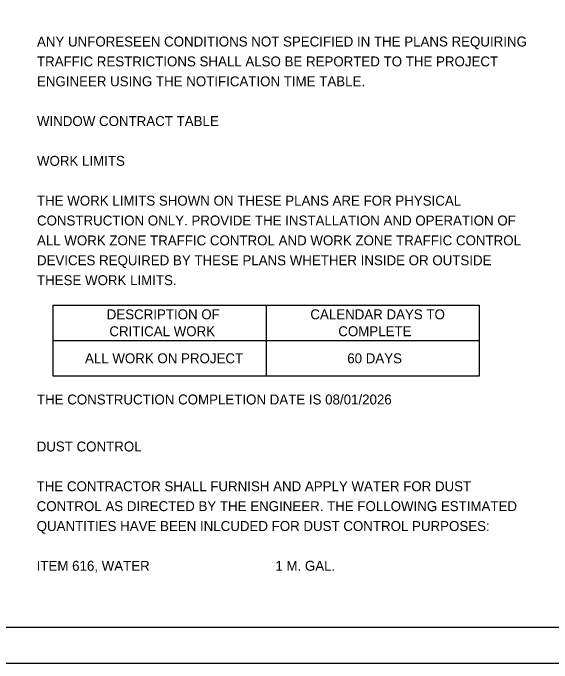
# Model space of a CAD drawing. Extents: x 0 to 34, y 0 to 22.
# Drawn here: x 16.9 to 24.49, y 0 to 9.15 of the extents above; entities that cross this region are included whole.
import ezdxf

# ---------------------------------------------------------------- set-up
doc = ezdxf.new("R2010")
doc.units = 0
for name, color, linetype in [('SH_Border', 7, 'Continuous'), ('SH_Cut_Line', 7, 'Continuous'), ('SH_Text', 7, 'Continuous')]:
    doc.layers.add(name, color=color, linetype=linetype)

msp = doc.modelspace()

# ---------------------------------------------------------------- linework, layer by layer
at = {"layer": 'SH_Border'}
msp.add_lwpolyline([(1.5, 21.5), (33.5, 21.5), (33.5, 0.5), (1.5, 0.5)], close=True, dxfattribs=at)
at = {"layer": 'SH_Cut_Line'}
msp.add_lwpolyline([(0, 0), (34, 0), (34, 22), (0, 22)], close=True, dxfattribs=at)
at = {"layer": 'SH_Text'}
for p, q in [((17.4658, 5.04), (23.4658, 5.04)), ((17.4658, 4.04), (17.4658, 5.04)), ((20.4658, 5.04), (20.4658, 4.04)), ((23.4658, 5.04), (23.4658, 4.04)), ((17.4658, 4.54), (23.4658, 4.54)), ((23.4658, 4.04), (17.4658, 4.04))]:
    msp.add_line(p, q, dxfattribs=at)

# ---------------------------------------------------------------- texts
for s, p in [('ANY UNFORESEEN CONDITIONS NOT SPECIFIED IN THE PLANS REQUIRING ', (17.24, 8.68)), ('TRAFFIC RESTRICTIONS SHALL ALSO BE REPORTED TO THE PROJECT ', (17.24, 8.4)), ('ENGINEER USING THE NOTIFICATION TIME TABLE.', (17.24, 8.12)), ('WINDOW CONTRACT TABLE', (17.24, 7.56)), ('WORK LIMITS', (17.24, 7)), ('THE WORK LIMITS SHOWN ON THESE PLANS ARE FOR PHYSICAL ', (17.24, 6.44)), ('CONSTRUCTION ONLY. PROVIDE THE INSTALLATION AND OPERATION OF ', (17.24, 6.16)), ('ALL WORK ZONE TRAFFIC CONTROL AND WORK ZONE TRAFFIC CONTROL ', (17.24, 5.88)), ('DEVICES REQUIRED BY THESE PLANS WHETHER INSIDE OR OUTSIDE ', (17.24, 5.6)), ('THESE WORK LIMITS.', (17.24, 5.32)), ('DESCRIPTION OF ', (18.2219, 4.839)), ('CALENDAR DAYS TO ', (21.0884, 4.839)), ('CRITICAL WORK', (18.2592, 4.601)), ('COMPLETE', (21.4817, 4.601)), ('ALL WORK ON PROJECT', (17.9159, 4.22)), ('60 DAYS', (21.6077, 4.22)), ('THE CONSTRUCTION COMPLETION DATE IS 08/01/2026', (17.24, 3.64)), ('DUST CONTROL', (17.2355, 2.9784)), ('THE CONTRACTOR SHALL FURNISH AND APPLY WATER FOR DUST', (17.2355, 2.4184)), ('CONTROL AS DIRECTED BY THE ENGINEER. THE FOLLOWING ESTIMATED ', (17.2355, 2.1384)), ('QUANTITIES HAVE BEEN INLCUDED FOR DUST CONTROL PURPOSES:', (17.2355, 1.8584)), ('ITEM 616, WATER', (17.2355, 1.2984)), ('1 M. GAL.', (20.5955, 1.2984))]:
    msp.add_text(s, height=0.14, dxfattribs=at).set_placement(p)

doc.saveas('drawing.dxf')
